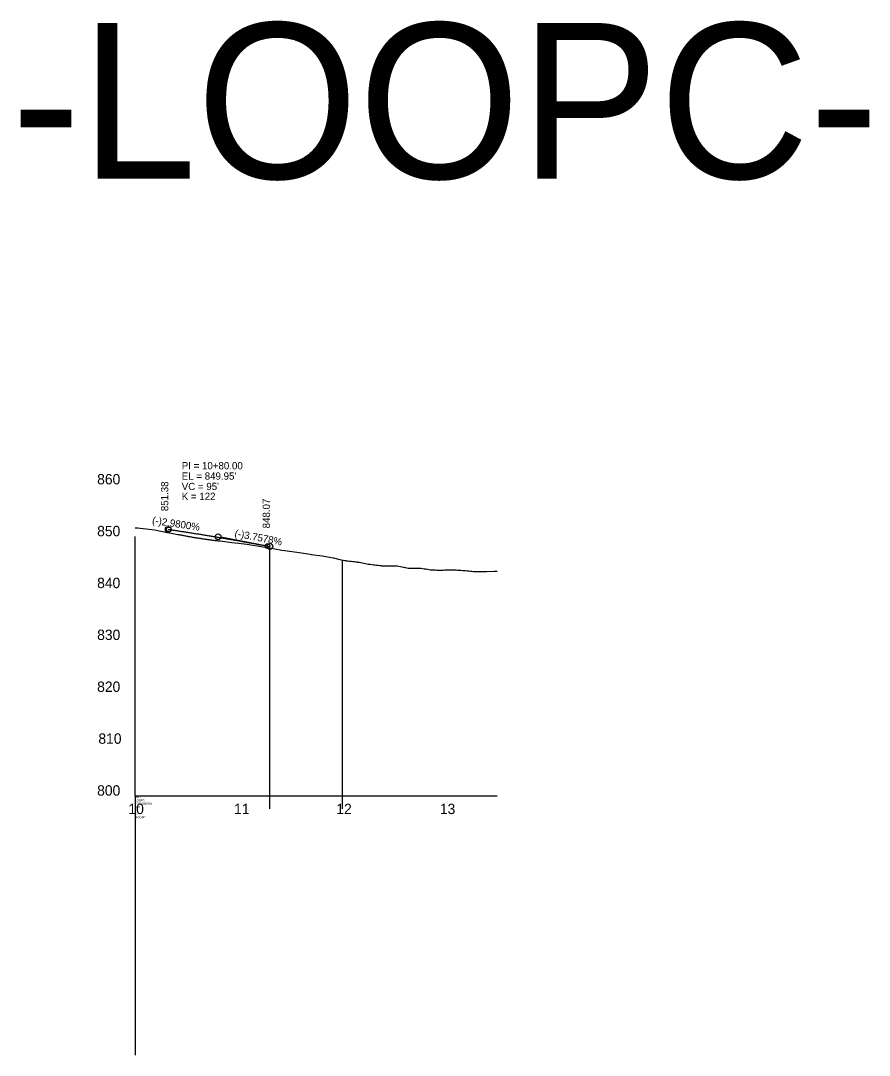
# Model space of a CAD drawing. Extents: x 570622 to 580296, y -55533 to -48575.
# Drawn here: x 575625 to 576443, y -55533 to -54536 of the extents above; entities that cross this region are included whole.
import ezdxf

# ---------------------------------------------------------------- set-up
doc = ezdxf.new("R2010")
doc.units = 0
for name, color, linetype in [('Default', 7, 'Continuous'), ('Exist Profile Cell', 7, 'Continuous'), ('Exist Vertical Profile Ground Line', 7, 'Continuous'), ('Exist Vertical Profile Horizontal Axis Label Major', 7, 'Continuous'), ('Exist Vertical Profile Vertical Axis Label', 7, 'Continuous'), ('Prop Vertical Profile Curve Label', 7, 'Continuous'), ('Prop Vertical Profile Grade', 7, 'Continuous'), ('Prop Vertical Profile Grade Label', 7, 'Continuous'), ('Prop VPI Label', 7, 'Continuous')]:
    doc.layers.add(name, color=color, linetype=linetype)

msp = doc.modelspace()

# ---------------------------------------------------------------- linework, layer by layer
at = {"layer": 'Default'}
for p, q in [((575864.83, -55295.26), (575864.83, -55043.65)), ((575934.83, -55295.26), (575934.83, -55055.72))]:
    msp.add_line(p, q, dxfattribs=at)
at = {"layer": 'Exist Profile Cell'}
for q in [(575734.83, -55032.76), (576083.78, -55282.76), (575734.83, -55532.76)]:
    msp.add_line((575734.83, -55282.76), q, dxfattribs=at)
at = {"layer": 'Exist Vertical Profile Ground Line'}
for points in [[(575734.83, -55024.34), (575737.57, -55024.28), (575737.63, -55024.28), (575739.81, -55024.73), (575753.99, -55026.33), (575758.06, -55027.16), (575776.1, -55030.7), (575776.87, -55030.85), (575777.64, -55031), (575778.42, -55031.15), (575779.19, -55031.3), (575779.96, -55031.45), (575780.73, -55031.59), (575781.5, -55031.74), (575782.27, -55031.89), (575783.04, -55032.03), (575783.81, -55032.17), (575784.59, -55032.32), (575785.36, -55032.46), (575786.13, -55032.6), (575786.9, -55032.74), (575787.67, -55032.88), (575788.44, -55033.02), (575789.21, -55033.16), (575789.98, -55033.3), (575790, -55033.3), (575790.76, -55033.43), (575791.53, -55033.57), (575792.3, -55033.7), (575792.4, -55033.72), (575793.07, -55033.82), (575793.84, -55033.94), (575794.61, -55034.06), (575795.38, -55034.17), (575796.15, -55034.29), (575796.93, -55034.4), (575797.19, -55034.44), (575797.7, -55034.52), (575798.47, -55034.64), (575799.24, -55034.75), (575800.01, -55034.87), (575800.78, -55034.98), (575801.55, -55035.1), (575802.33, -55035.21), (575803.1, -55035.32), (575803.87, -55035.43), (575804.64, -55035.54), (575805.41, -55035.65), (575806.18, -55035.75), (575806.95, -55035.86), (575807.72, -55035.96), (575808.5, -55036.07), (575809.27, -55036.17), (575810.04, -55036.27), (575810.77, -55036.36), (575810.81, -55036.37), (575811.58, -55036.46), (575812.35, -55036.55), (575813.12, -55036.63), (575813.89, -55036.72), (575814.67, -55036.8), (575816.83, -55037.04), (575828.03, -55038.43), (575834.43, -55039.19), (575842.59, -55040.05), (575858.29, -55042.57), (575862.84, -55043.27), (575876.15, -55045.8), (575879.23, -55046.17), (575892.9, -55048.12), (575903.74, -55049.94), (575904.4, -55050), (575915.13, -55051.27), (575925.72, -55053.42), (575925.99, -55053.47), (575932.31, -55054.87), (575933.84, -55055.22), (575935.37, -55055.56), (575936.91, -55055.9), (575937.21, -55055.97), (575937.51, -55056.02), (575938.44, -55056.13), (575939.97, -55056.3), (575941.51, -55056.47), (575943.04, -55056.64), (575944.57, -55056.81), (575946.1, -55056.99), (575947.64, -55057.16), (575948.6, -55057.27), (575948.97, -55057.33), (575949.17, -55057.37), (575950.7, -55057.65), (575952.24, -55057.94), (575953.77, -55058.22), (575955.3, -55058.51), (575956.83, -55058.79), (575958.37, -55059.08), (575959.47, -55059.28), (575959.83, -55059.34), (575959.9, -55059.35), (575961.43, -55059.54)], [(575961.43, -55059.54), (575962.97, -55059.73), (575964.5, -55059.92), (575966.03, -55060.1), (575967.56, -55060.29), (575969.1, -55060.48), (575970.63, -55060.67), (575972.16, -55060.86), (575972.38, -55060.88), (575972.59, -55060.9), (575973.7, -55060.91), (575975.23, -55060.91), (575976.76, -55060.92), (575978.29, -55060.92), (575979.83, -55060.93), (575981.36, -55060.94), (575982.89, -55060.94), (575984.43, -55060.94), (575985.96, -55060.95), (575987.04, -55060.95), (575987.11, -55060.96), (575987.49, -55061.04), (575989.02, -55061.34), (575990.56, -55061.64), (575992.09, -55061.94), (575993.62, -55062.24), (575994.08, -55062.33), (575995.16, -55062.55), (575996.69, -55062.87), (575998.13, -55063.17), (575998.22, -55063.18), (575998.31, -55063.18), (575999.75, -55063.18), (576001.29, -55063.18), (576001.77, -55063.18), (576002.82, -55063.19), (576004.35, -55063.21), (576005.89, -55063.22), (576007.42, -55063.24), (576008.95, -55063.25), (576010.19, -55063.26), (576010.33, -55063.26), (576010.48, -55063.29), (576012.02, -55063.53), (576013.55, -55063.77), (576015.08, -55064.01), (576016.62, -55064.25), (576016.99, -55064.31), (576018.15, -55064.5), (576019.68, -55064.75), (576021.16, -55065), (576021.21, -55065), (576021.3, -55065), (576022.75, -55065.02), (576024.28, -55065.04), (576025.81, -55065.06), (576027.35, -55065.08), (576028.88, -55065.11), (576030.41, -55065.13), (576030.48, -55065.13), (576030.5, -55065.14), (576031.94, -55065.08), (576033.23, -55065.04), (576033.48, -55065.03), (576034.37, -55065), (576035.01, -55064.98), (576036.54, -55064.93), (576038.08, -55064.88), (576039.61, -55064.84), (576040.96, -55064.81), (576041.02, -55064.8), (576041.14, -55064.81), (576042.67, -55064.9), (576044.21, -55065), (576045.74, -55065.09), (576047.27, -55065.19), (576048.81, -55065.29), (576050.34, -55065.39), (576051.64, -55065.48), (576051.66, -55065.48), (576051.87, -55065.5), (576052.69, -55065.58), (576053.41, -55065.66), (576054.94, -55065.82), (576056.47, -55065.97), (576058, -55066.13), (576059.54, -55066.29), (576061.07, -55066.45), (576062.6, -55066.61), (576062.86, -55066.64), (576062.94, -55066.64), (576072.59, -55066.41), (576073.59, -55066.43), (576080.85, -55066.19), (576083.78, -55066.05)]]:
    msp.add_lwpolyline(points, dxfattribs=at)
at = {"layer": 'Prop Vertical Profile Curve Label'}
for centre in [(575767.33, -55025.93), (575862.33, -55041.93)]:
    msp.add_circle(centre, 2.25, dxfattribs=at)
at = {"layer": 'Prop Vertical Profile Grade'}
for p, q in [((575766.83, -55025.85), (575767.33, -55025.93)), ((575862.33, -55041.93), (575864.83, -55042.4))]:
    msp.add_line(p, q, dxfattribs=at)
msp.add_spline([(575767.33, -55025.93), (575769.23, -55026.21), (575771.13, -55026.5), (575773.03, -55026.78), (575774.93, -55027.07), (575776.83, -55027.36), (575778.73, -55027.65), (575780.63, -55027.95), (575782.53, -55028.24), (575784.43, -55028.54), (575786.33, -55028.83), (575788.23, -55029.13), (575790.13, -55029.43), (575792.03, -55029.73), (575793.93, -55030.04), (575795.83, -55030.34), (575797.73, -55030.65), (575799.63, -55030.96), (575801.53, -55031.26), (575803.43, -55031.57), (575805.33, -55031.89), (575807.23, -55032.2), (575809.13, -55032.51), (575811.03, -55032.83), (575812.93, -55033.15), (575814.83, -55033.47), (575816.73, -55033.79), (575818.63, -55034.11), (575820.53, -55034.44), (575822.43, -55034.76), (575824.33, -55035.09), (575826.23, -55035.42), (575828.13, -55035.74), (575830.03, -55036.08), (575831.93, -55036.41), (575833.83, -55036.74), (575835.73, -55037.08), (575837.63, -55037.42), (575839.53, -55037.75), (575841.43, -55038.09), (575843.33, -55038.44), (575845.23, -55038.78), (575847.13, -55039.12), (575849.03, -55039.47), (575850.93, -55039.82), (575852.83, -55040.16), (575854.73, -55040.52), (575856.63, -55040.87), (575858.53, -55041.22), (575860.43, -55041.57), (575862.33, -55041.93)], degree=3, dxfattribs=at)
at = {"layer": 'Prop VPI Label'}
for p, q in [((575767.33, -55025.93), (575812.11, -55032.6)), ((575862.33, -55041.93), (575817.53, -55033.51))]:
    msp.add_line(p, q, dxfattribs=at)
for centre in [(575766.83, -55025.85), (575814.83, -55033.01), (575864.83, -55042.4)]:
    msp.add_circle(centre, 2.75, dxfattribs=at)

# ---------------------------------------------------------------- texts
at = {"layer": 'Default'}
msp.add_text('-LOOPC-', height=150, dxfattribs=at).set_placement((575615.65, -54687.88))
at = {"layer": 'Exist Profile Cell'}
for s, p in [('1000.000000', (575734.83, -55291.26)), ('RDY', (575734.83, -55284.76)), ('LOOPC', (575734.83, -55288.01)), ('800', (575734.83, -55294.51)), ('2', (575734.83, -55301.01)), ('10', (575734.83, -55297.76)), ('NOGAP', (575734.83, -55304.26))]:
    msp.add_text(s, height=2, dxfattribs=at).set_placement(p)
at = {"layer": 'Exist Vertical Profile Horizontal Axis Label Major'}
for s, p in [('10', (575728.41, -55300.26)), ('10', (575728.41, -55300.26)), ('11', (575830.25, -55300.26)), ('11', (575830.25, -55300.26)), ('12', (575928.8, -55300.26)), ('12', (575928.8, -55300.26)), ('13', (576028.64, -55300.26))]:
    msp.add_text(s, height=10, dxfattribs=at).set_placement(p)
at = {"layer": 'Exist Vertical Profile Vertical Axis Label'}
for s, p in [('860', (575698.26, -54982.51)), ('860', (575698.26, -54982.51)), ('850', (575698.26, -55032.51)), ('850', (575698.26, -55032.51)), ('840', (575698.26, -55082.51)), ('840', (575698.26, -55082.51)), ('830', (575698.26, -55132.51)), ('830', (575698.26, -55132.51)), ('820', (575698.26, -55182.51)), ('820', (575698.26, -55182.51)), ('810', (575699.46, -55232.51)), ('810', (575699.46, -55232.51)), ('800', (575698.26, -55282.51)), ('800', (575698.26, -55282.51))]:
    msp.add_text(s, height=10, dxfattribs=at).set_placement(p)
at = {"layer": 'Prop Vertical Profile Curve Label'}
for s, p in [("VC = 95'", (575779.83, -54988.01)), ('K = 122', (575779.83, -54997.54))]:
    msp.add_text(s, height=7, dxfattribs=at).set_placement(p)
at = {"layer": 'Prop Vertical Profile Grade Label'}
for s, rotation, p in [('(-)2.9800%', 351.52528, (575750.91, -55020.45)), ('(-)3.7578%', 349.35876, (575830.32, -55032.86))]:
    msp.add_text(s, height=7, rotation=rotation, dxfattribs=at).set_placement(p)
at = {"layer": 'Prop VPI Label'}
for s, p in [('PI = 10+80.00', (575779.83, -54968.01)), ("EL = 849.95'", (575779.83, -54978.01))]:
    msp.add_text(s, height=7, dxfattribs=at).set_placement(p)
for s, p in [('851.38', (575766.83, -55008.35)), ('848.07', (575864.83, -55024.9))]:
    msp.add_text(s, height=7, rotation=90, dxfattribs=at).set_placement(p)

doc.saveas('drawing.dxf')
